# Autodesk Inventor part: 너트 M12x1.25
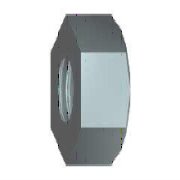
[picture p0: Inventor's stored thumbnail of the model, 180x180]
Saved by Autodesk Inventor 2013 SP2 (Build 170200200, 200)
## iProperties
IsCustomPart: 0
Created: 2015-12
Part Number: 너트 M12x1.25
Material: 스테인리스강
Description: 6각 너트
Document SubType Name: Modeling
Standard: KS B 1012
Designer: mdu
Standards Organization: KS
Language: ko-KR
Size Designation: M12x1.25
Categories: <MemberInstance><Categories><Category DisplayName="조임쇠" InternalName="e4da775c-781d-43d5-af7c-5136215cf5a6" Mnemonic="FSTN"><Category DisplayName="너트" InternalN
Density: 8.08 g/cm^3
Author: mdu
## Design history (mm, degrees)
sketch "스케치1"
  geometry: L1 (10.97, 0)-(5.485, -9.5); L2 (5.485, -9.5)-(-5.485, -9.5); L3 (-5.485, -9.5)-(-10.97, 0); L4 (-10.97, 0)-(-5.485, 9.5); L5 (-5.485, 9.5)-(5.485, 9.5); L6 (5.485, 9.5)-(10.97, 0); 2 further points
  constraints: 12 end point, 1 coincident, 1 horizontal, 11 other
  dimensions: "d0" = 21.93931 distance of L1.start L3.end (= 1.1547 x SW)
extrude "본체" new body sketch "스케치1" distance "d1" = 10 (= KOH); taper "d2" = 0 deg
sketch "스케치2"
  geometry: 1 further point
hole "스레드" sketch "스케치2" diameter "d6" = 10.647; stored, may be unused: countersink angle "d10" = 82 deg, drill point angle "d12" = 118 deg; dims "d7" = 12.7, "d8" = 9.525, "d9" = 6.35, "d11" = 19.05
sketch "스케치3"
  geometry: L1 (0, 10.97)-(10, 10.97) reference; L2 (10, 5.485)-(10, 10.97) reference; L3 (-2, 0)-(12, 0) reference; L4 (9.151, 10.97)-(10, 9.5)
  constraints: 2 end point, 2 point on line
  dimensions: "d3" = 19 diameter of L4.end L3 (= SW01); "d4" = 30 deg angle of L2 L4 (= ANG2)
revolve "모따기3" sketch "스케치3" stored, may be unused: angle "d5" = 90 deg
workaxis "Work Axis1"
workplane "Work Plane1"
body "Solid1"
chamfer "모따기1" distance "d13" = 0.67658 (= -0.5 x GD1 + 0.5 x NND); stored, may be unused: angle "d14" = 30 deg, second distance "d21" = 0.67658 (= -0.5 x GD1 + 0.5 x NND)
chamfer "모따기2" distance "d15" = 0.67658 (= -0.5 x GD1 + 0.5 x NND); stored, may be unused: angle "d16" = 30 deg, second distance "d22" = 0.67658 (= -0.5 x GD1 + 0.5 x NND)
other parameters: "ANG2" = 30 deg [user parameter; used in 1 equation term], "NND" = 12 [user parameter; used in 4 equation terms], "KOH" = 10 [user parameter; used in 1 equation term], "SW" = 19 [user parameter; used in 3 equation terms], "SW01" = 19 (= SW) [user parameter; used in 1 equation term], "GD1" = 10.64684 (computed from THREADDIA, PTC, TOA) [user parameter; used in 4 equation terms], "d19" = 0, "d20" = 0, "d24" = 0, "d25" = 0, "GUL" = 0.67658 (= 0.541266 x PTC) [user parameter], "TPU" = 8 (computed from PTC) [user parameter], "TOA" = 30 deg [user parameter; used in 1 equation term], "PTC" = 1.25 [user parameter; used in 4 equation terms], "E0" = 21.945 (= 1.155 x SW) [user parameter], "THREADDIA" = 12 [user parameter; used in 1 equation term], "GAL" = 0.67658 (= 0.541266 x PTC) [user parameter]
